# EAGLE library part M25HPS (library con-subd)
SUB-D
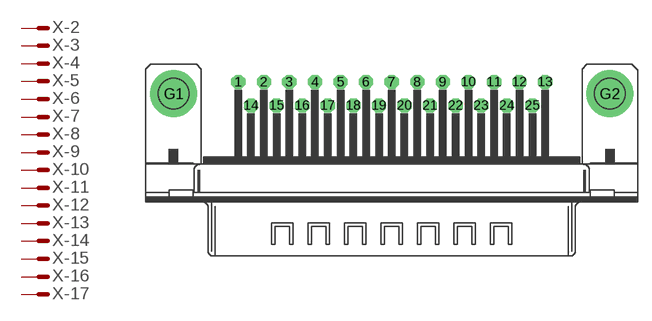
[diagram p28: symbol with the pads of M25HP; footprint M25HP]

Designator prefix X; gates -2=M -3=M -4=M -5=M -6=M -7=M -8=M -9=M -10=M -11=M -12=M -13=M -14=M -15=M -16=M -17=M -18=M -19=M -20=M -21=M -22=M -23=M -24=M -25=M -G=GND -1=MV

## M25HPS (OC_FARNELL: unknown; OC_NEWARK: unknown)  [M25HP]
1  -1:M  pas
2  -2:M  pas
3  -3:M  pas
4  -4:M  pas
5  -5:M  pas
6  -6:M  pas
7  -7:M  pas
8  -8:M  pas
9  -9:M  pas
10  -10:M  pas
11  -11:M  pas
12  -12:M  pas
13  -13:M  pas
14  -14:M  pas
15  -15:M  pas
16  -16:M  pas
17  -17:M  pas
18  -18:M  pas
19  -19:M  pas
20  -20:M  pas
21  -21:M  pas
22  -22:M  pas
23  -23:M  pas
24  -24:M  pas
25  -25:M  pas
G1  -G:G1  pas
G2  -G:G2  pas

## Footprint M25HP (pad centres in mm)
SUB-D
drill 1.016 octagon: 1 -16.561,1.27; 2 -13.792,1.27; 3 -11.049,1.27; 4 -8.28,1.27; 5 -5.512,1.27; 6 -2.769,1.27; 7 0,1.27; 8 2.769,1.27; 9 5.512,1.27; 10 8.28,1.27; 11 11.049,1.27; 12 13.792,1.27; 13 16.561,1.27; 14 -15.189,-1.27; 15 -12.421,-1.27; 16 -9.652,-1.27; 17 -6.909,-1.27; 18 -4.14,-1.27; 19 -1.372,-1.27; 20 1.372,-1.27; 21 4.14,-1.27; 22 6.909,-1.27; 23 9.652,-1.27; 24 12.421,-1.27; 25 15.189,-1.27
drill 3.302 pad 5.08 round: G1 -23.52,0; G2 23.52,0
